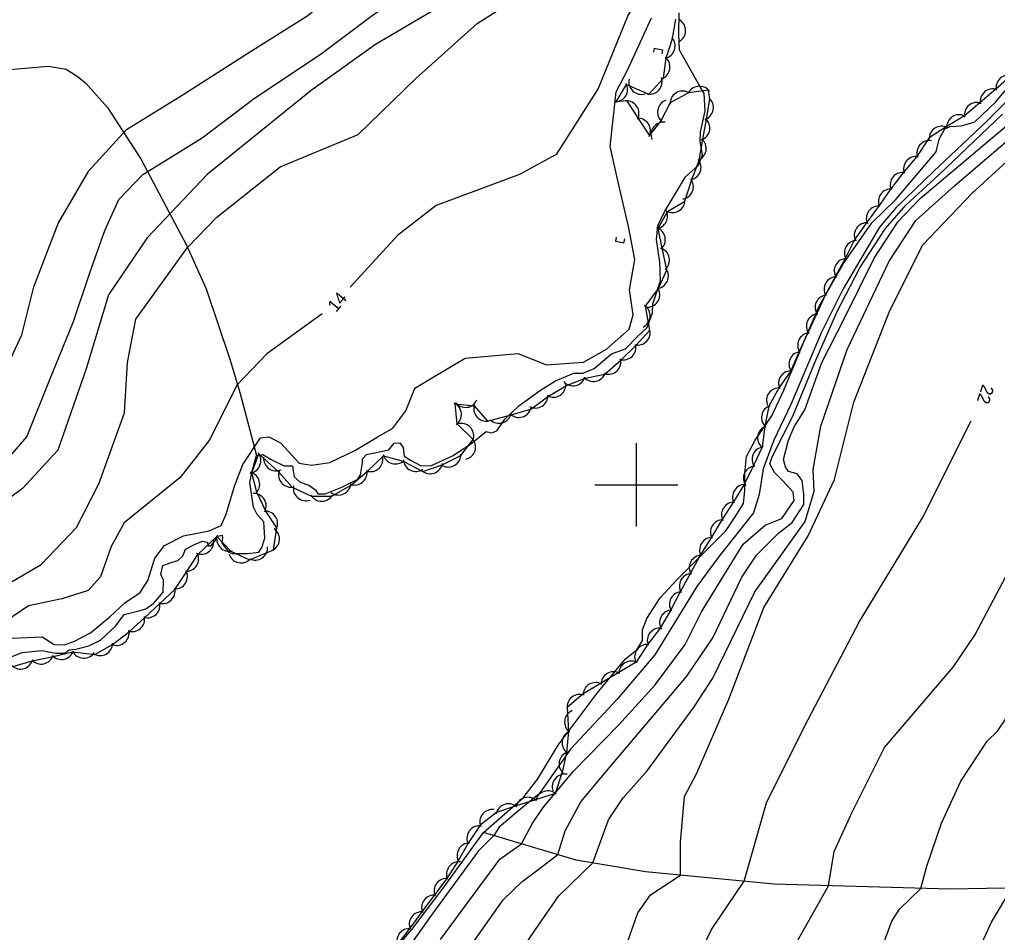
# Model space of a CAD drawing. Extents: x 646142 to 649934, y 5874075 to 5876351.
# Drawn here: x 648451.8 to 648686.8, y 5875292.5 to 5875511.8 of the extents above; entities that cross this region are included whole.
import ezdxf

# ---------------------------------------------------------------- set-up
doc = ezdxf.new("R2010")
doc.units = 0
for name, color, linetype in [('Niveau 1', 7, 'Continuous'), ('Niveau 2', 7, 'Continuous'), ('Niveau 26', 7, 'Continuous'), ('Niveau 4', 7, 'Continuous'), ('Niveau 44', 7, 'Continuous'), ('Niveau 61', 7, 'Continuous')]:
    doc.layers.add(name, color=color, linetype=linetype)

msp = doc.modelspace()

# ---------------------------------------------------------------- linework, layer by layer
at = {"layer": 'Niveau 1'}
for points in [[(648446.52, 5875403.47), (648453.53, 5875411.53), (648458.94, 5875424.95), (648464.76, 5875439.28), (648468.71, 5875450.92), (648472.32, 5875461.15), (648475.67, 5875468.58), (648481.42, 5875474.59), (648495.69, 5875483.36), (648508.29, 5875492.92), (648524.03, 5875503.43), (648536.21, 5875512.49), (648556.03, 5875526.54), (648567.28, 5875535.53), (648573.52, 5875544.1), (648582.86, 5875551.08), (648596.63, 5875560.03), (648610.78, 5875566.93), (648623.12, 5875576.45), (648636.69, 5875591.14), (648643.13, 5875598.74), (648651.26, 5875607.45), (648666.17, 5875621.46), (648679.59, 5875631.12)], [(648592.7, 5875275.42), (648600.38, 5875297.2), (648603.37, 5875301.49), (648610.59, 5875306.26), (648610.58, 5875314.15), (648611.6, 5875325.18), (648614.45, 5875330.61), (648622.21, 5875348.51), (648630.6, 5875370.52), (648641.28, 5875387.77), (648647.59, 5875401.32), (648652.28, 5875419.91), (648660.88, 5875441.9), (648668.86, 5875457.71), (648680.66, 5875470.07), (648694.75, 5875482.88), (648710.43, 5875501.6), (648716.29, 5875506.83)]]:
    msp.add_lwpolyline(points, dxfattribs=at)
at = {"layer": 'Niveau 2'}
for points in [[(648773.24, 5875660.13), (648771.63, 5875657.22), (648765.49, 5875651.86), (648760.19, 5875648.97), (648749.57, 5875645.79), (648733.26, 5875640.93), (648712.53, 5875636.85), (648693.47, 5875629.74), (648674.98, 5875618.92), (648656.72, 5875602.7), (648643.07, 5875587.36), (648618.42, 5875563.73), (648594.18, 5875540.59), (648565.49, 5875522.47), (648537.36, 5875505.81), (648521.88, 5875494.75), (648496.86, 5875474.58), (648482.48, 5875459.38), (648473.15, 5875445.67), (648467.81, 5875427.88), (648460.98, 5875408.35), (648452.47, 5875399.1), (648430.65, 5875382.97)], [(648751.16, 5875635.11), (648742.73, 5875629.52), (648734.81, 5875627.4), (648724.79, 5875625.09), (648709.54, 5875619.48), (648694.13, 5875610.32), (648675.4, 5875598.74), (648662.52, 5875584.84), (648654.97, 5875574.48), (648637.37, 5875558.02), (648621.93, 5875546.24), (648610.99, 5875534.16), (648598.03, 5875512.9), (648590.87, 5875495.22), (648580.72, 5875479.4), (648571.95, 5875474.59), (648551.87, 5875467.11), (648542.6, 5875459.89), (648531.28, 5875447.47)], [(648442.65, 5875372.58), (648456.97, 5875380.91), (648465.46, 5875389.73), (648470.84, 5875400.27), (648477.03, 5875417.31), (648477.73, 5875429.43), (648479.72, 5875439.79), (648492.14, 5875457.01), (648499.2, 5875464.3), (648514.42, 5875476.42), (648533.17, 5875484.19), (648546.9, 5875497.57), (648561.79, 5875510.81), (648580.89, 5875522.99), (648598.86, 5875537.86), (648613.32, 5875553.6), (648629.07, 5875567.35), (648649.25, 5875589.33), (648661.93, 5875600.98), (648676.7, 5875615.34), (648699.11, 5875628.2), (648705.3, 5875630.04)], [(648444.89, 5875420.22), (648452.31, 5875436.05), (648455.23, 5875447.59), (648461.09, 5875462.83), (648468.41, 5875475.42), (648477.53, 5875485.38), (648490.9, 5875493.61), (648507.31, 5875504.15), (648521.1, 5875512.75), (648525.4, 5875516.56), (648530.21, 5875524.32), (648533.29, 5875532.06), (648533.37, 5875536.39)], [(648546.75, 5875423.22), (648552.38, 5875426.58), (648558.9, 5875430.42), (648571.51, 5875431.56), (648578.45, 5875428.87), (648587.29, 5875429.47), (648592.82, 5875432.59), (648598.29, 5875437.39), (648599.24, 5875440.89), (648598.33, 5875446.85), (648599.63, 5875454.15), (648598.12, 5875462.04), (648595.74, 5875472.41), (648593.69, 5875481.3), (648595.14, 5875494.43), (648597.97, 5875499.76), (648603.61, 5875512.17)], [(648697.21, 5875500.45), (648684, 5875487.18), (648671.38, 5875475.27), (648662.47, 5875466.65), (648658.41, 5875461.89), (648649.69, 5875447.12), (648644.48, 5875436.69), (648637.09, 5875419.35), (648633.04, 5875410.71), (648630.48, 5875403.89), (648629.51, 5875397.71), (648628.15, 5875393.28), (648619.88, 5875382.91), (648614.53, 5875375.57), (648604.46, 5875359.18), (648595.5, 5875348.63), (648584.21, 5875336.53), (648576.69, 5875325.77), (648571.74, 5875321.81), (648567.03, 5875317.77), (648565.8, 5875315.74), (648562.04, 5875312.06), (648551.13, 5875297.15), (648545.6, 5875289.33)], [(648635.88, 5875404.37), (648635.37, 5875406.11), (648635.37, 5875406.11), (648636.59, 5875410.75), (648637.94, 5875413.98), (648640.51, 5875418.04), (648644.54, 5875429.39), (648649.95, 5875439.88), (648657.12, 5875454.47), (648662.93, 5875463.27), (648668.2, 5875468.82), (648678.92, 5875477.82), (648690.08, 5875487.21)], [(648653.73, 5875452.15), (648659.84, 5875461.58), (648664.76, 5875467.23), (648672.72, 5875474.45), (648688.02, 5875489.07)], [(648569.38, 5875283.74), (648575.8, 5875293.16), (648581.4, 5875301.31), (648589.58, 5875309.17), (648593.32, 5875319.5), (648596.83, 5875324.84), (648602.58, 5875331.34), (648613.87, 5875346.71), (648618.41, 5875353.57), (648628.5, 5875374.28), (648635.8, 5875384.51), (648640.6, 5875391.17), (648642.74, 5875398.51), (648642.5, 5875403.71), (648644.36, 5875414.11), (648650.67, 5875432.54), (648660.77, 5875453.75), (648667.18, 5875463.53), (648676.53, 5875471.92), (648692.46, 5875485.5)], [(648622.07, 5875247.3), (648629.59, 5875266.23), (648638.01, 5875289.19), (648646.2, 5875303.69), (648647.54, 5875311.94), (648651.78, 5875321.22), (648659.66, 5875336.91), (648676.17, 5875356.24), (648681.3, 5875363.87), (648690.29, 5875380.85), (648717.14, 5875420.67), (648722.82, 5875430.35), (648724.42, 5875434.72), (648725.25, 5875441.14), (648724.29, 5875451.86), (648726.2, 5875464.49)], [(648552.94, 5875290.82), (648567.2, 5875310.09), (648572.39, 5875313.77), (648575.01, 5875318.55), (648577.6, 5875322.5), (648584.94, 5875331.21), (648595.71, 5875342.28), (648604.5, 5875351.97), (648611.75, 5875361.63), (648615.63, 5875369.52), (648622.3, 5875380.31), (648625.69, 5875385.77), (648630.94, 5875390.34), (648634.93, 5875391.93), (648637.95, 5875396.29), (648637.65, 5875398.28), (648635.28, 5875400.9), (648633.2, 5875402.96), (648632.05, 5875405.1), (648632.61, 5875406.71), (648637.61, 5875416.5), (648642.91, 5875429.43), (648648.2, 5875441.47), (648653.73, 5875452.15)], [(648524.51, 5875441.07), (648511.25, 5875431.51), (648503.97, 5875423.96), (648497.56, 5875410.91), (648490.4, 5875401.74), (648476.91, 5875390.9)], [(648450.04, 5875363.15), (648457.23, 5875363.51), (648460.13, 5875361.66), (648462.51, 5875361.54), (648464.86, 5875362.37), (648468.86, 5875364.44), (648473.47, 5875368.3), (648477.06, 5875371.7), (648480.8, 5875374.11), (648482.59, 5875377.03), (648484.28, 5875382.39), (648486.6, 5875385.42), (648491.17, 5875387.73), (648497.33, 5875388.95), (648500.23, 5875390.25), (648501.46, 5875392.94), (648503.48, 5875399.71), (648505.48, 5875404.92), (648509.73, 5875411.31), (648511.73, 5875411.51), (648514.52, 5875410.12), (648518.95, 5875405.26), (648521.97, 5875404.77), (648526.36, 5875405.38), (648532.53, 5875408.35), (648537.74, 5875411.44), (648541.48, 5875413.61), (648544.62, 5875417.81), (648546.83, 5875423.43)], [(648558.35, 5875144.51), (648561.02, 5875146.56), (648564.53, 5875149.52), (648567.42, 5875152.64), (648570.45, 5875164.8), (648576.75, 5875176.03), (648582.31, 5875187.66), (648596.54, 5875228.87), (648603.08, 5875255.94), (648608.57, 5875273.45), (648618.1, 5875293.2), (648625.88, 5875304.77), (648631.24, 5875323.66), (648640.41, 5875341.95), (648653.65, 5875367.19), (648668.78, 5875392.12), (648680.45, 5875415.43)], [(648558.6, 5875287), (648567.97, 5875300.29), (648572.51, 5875304.66), (648576.04, 5875307.27), (648581.1, 5875311.17), (648582.92, 5875316.93), (648586.64, 5875323.84), (648593.53, 5875332.13), (648604.69, 5875345.25), (648612.12, 5875354.08), (648618.35, 5875363.26), (648625.37, 5875377.87), (648628.89, 5875383.1), (648634.18, 5875388.39), (648637.48, 5875390.98), (648640.26, 5875395.3), (648640.27, 5875397.8), (648639.85, 5875401.09), (648638.64, 5875402.63), (648636.58, 5875403.25), (648635.88, 5875404.37)], [(648476.91, 5875390.9), (648473.78, 5875385.22), (648471.27, 5875377.94), (648468.27, 5875374.67), (648461.97, 5875372.6), (648453.96, 5875370.97), (648448.41, 5875367.19)], [(648684.3, 5875338.42), (648686.77, 5875340.87), (648688.94, 5875344.01)], [(648625.98, 5875139.41), (648626.24, 5875144.08), (648628.96, 5875152.5), (648633.52, 5875169.83), (648636.38, 5875194.48), (648640.24, 5875216.68), (648642.14, 5875240.62), (648644.45, 5875250.49), (648649.68, 5875266), (648653.41, 5875273.59), (648661.4, 5875295.19), (648663.26, 5875298.06), (648668.38, 5875303.05), (648669.83, 5875308.41), (648673.35, 5875318.75), (648677.94, 5875328.85), (648684.3, 5875338.42)], [(648669.21, 5875174.05), (648673.22, 5875194.68), (648676.22, 5875210.96), (648681.89, 5875239.25), (648682.27, 5875249.4), (648680.98, 5875254.69), (648678.96, 5875264.27), (648678.37, 5875270.92), (648679.53, 5875278.9), (648682.11, 5875287.95), (648685.34, 5875294.94), (648690.22, 5875303.15), (648690.77, 5875307.43), (648692.74, 5875314.18), (648696.01, 5875323.29), (648699.48, 5875330.17), (648701.55, 5875334.47)]]:
    msp.add_lwpolyline(points, dxfattribs=at)
at = {"layer": 'Niveau 26'}
for p, q in [((648604.3, 5875504.94), (648604.11, 5875503.96)), ((648604.3, 5875504.94), (648606.28, 5875504.55)), ((648606.28, 5875504.55), (648606.09, 5875503.57)), ((648595.05, 5875458.51), (648595.25, 5875459.49)), ((648597.03, 5875458.11), (648597.23, 5875459.09)), ((648597.03, 5875458.11), (648595.05, 5875458.51))]:
    msp.add_line(p, q, dxfattribs=at)
at = {"layer": 'Niveau 4'}
for points in [[(648555.81, 5875406.98), (648560.16, 5875409.81), (648563.91, 5875412.81), (648565.25, 5875412.47), (648566.51, 5875412.95), (648568.37, 5875415.77), (648571.75, 5875418.97), (648576.97, 5875422.72), (648580.55, 5875424.99), (648584.99, 5875426.87), (648587.13, 5875426.84), (648589.87, 5875427.96), (648594.04, 5875431.48), (648597.37, 5875432.65), (648600.26, 5875435.67), (648602.63, 5875437.84), (648603.87, 5875441.31), (648603.94, 5875443.52), (648604.61, 5875445.43), (648605.84, 5875449.02), (648605.62, 5875453.53), (648604.87, 5875458.93), (648605.2, 5875462.21), (648606.8, 5875465.59), (648611.82, 5875474.01), (648614.96, 5875476.82), (648615.92, 5875479.33), (648615.34, 5875482.54), (648615.4, 5875484.75), (648616.52, 5875489.84), (648616.33, 5875494), (648615.28, 5875495.77), (648610.36, 5875504.44), (648610.19, 5875508.38), (648610.28, 5875513.38)], [(648447.65, 5875499.66), (648458.71, 5875500.56), (648463.03, 5875499.91), (648465.74, 5875498.11), (648467.65, 5875496.61), (648472.97, 5875490.68), (648481, 5875478.14), (648491.9, 5875457.61), (648496.62, 5875447.14), (648502.29, 5875430.2), (648504.8, 5875421.96), (648508.77, 5875407.04)], [(648609.73, 5875377.2), (648621.54, 5875389), (648623.72, 5875392.33), (648625.79, 5875395.52), (648626.09, 5875398.65), (648626.06, 5875402.83), (648626.51, 5875406.81), (648628.52, 5875410.71), (648632.59, 5875416.61), (648635.46, 5875422.74), (648640.52, 5875434.95), (648643.94, 5875442.97), (648649.76, 5875453.22), (648656.57, 5875462.97), (648662.33, 5875468.58), (648672.06, 5875480.01), (648672.73, 5875483.04), (648674.16, 5875485.54), (648675.41, 5875486.12), (648678.11, 5875486.25), (648681.33, 5875487.25), (648686.34, 5875491.96), (648693.81, 5875500.81)], [(648463.76, 5875360.39), (648465.29, 5875360.54), (648468.41, 5875361.33), (648471.25, 5875362.69), (648474.94, 5875366.16), (648476.94, 5875368.87), (648480.76, 5875369.85), (648482.14, 5875370.23), (648484.03, 5875371.61), (648486.27, 5875374.22), (648486.35, 5875377.1), (648485.75, 5875378.47), (648486.25, 5875380.67), (648488.2, 5875381.34), (648489.81, 5875381.86), (648491.01, 5875382.93), (648491.69, 5875384.55), (648493.83, 5875385.72), (648495.77, 5875386.52), (648496.98, 5875386.28), (648497.07, 5875385.33), (648497.77, 5875385.4), (648498.74, 5875386.45), (648499.45, 5875387.72), (648500.49, 5875387.94), (648500.56, 5875387.23), (648500.44, 5875386.03), (648502.07, 5875383.8), (648502.92, 5875383.53), (648506.59, 5875383.54), (648509.29, 5875383.81), (648510.01, 5875384.96), (648510.75, 5875387.18), (648510.5, 5875391.1), (648508.92, 5875392.85), (648508.03, 5875394.67), (648507.13, 5875400.55), (648507.79, 5875403.6), (648508.77, 5875407.04), (648510.28, 5875407.31), (648512.29, 5875406.08), (648515.39, 5875404.6), (648517.41, 5875404.57), (648517.52, 5875403.38), (648517.77, 5875401.97), (648519.2, 5875400.68), (648521.28, 5875399.94), (648522.93, 5875398.79), (648523.49, 5875397.89), (648525.27, 5875397.83), (648529.27, 5875399.43), (648533.11, 5875401.36), (648533.73, 5875402.38), (648534.17, 5875405.29), (648534.2, 5875406.25), (648535.16, 5875407.3), (648540.51, 5875408.43), (648541.78, 5875410), (648543.19, 5875410.14), (648544.01, 5875409.02), (648544.21, 5875406.89), (648545.71, 5875405.97), (648548.33, 5875404.56), (648550.81, 5875404.69), (648555.81, 5875406.98)], [(648538.93, 5875284.84), (648546.07, 5875293.18), (648553.55, 5875303.11), (648563.3, 5875316.49), (648572.82, 5875324.83), (648576.3, 5875329.35), (648581.23, 5875337.48), (648590.6, 5875349.99), (648597.41, 5875358.19), (648600.16, 5875360.37), (648601.49, 5875362.65), (648601.49, 5875365.16), (648602.54, 5875367.89), (648605.75, 5875372.86), (648609.73, 5875377.2)], [(648446.29, 5875357.32), (648452.45, 5875359.73), (648457.15, 5875360.2), (648460.52, 5875359.59), (648462.66, 5875359.56), (648463.76, 5875360.39)], [(648785.38, 5875300.42), (648761.34, 5875301.73), (648735.42, 5875302.25), (648710.3, 5875303.55), (648675.42, 5875302.85), (648633.06, 5875304.07), (648602.22, 5875307.07), (648585.58, 5875309.83), (648563.3, 5875316.49)]]:
    msp.add_lwpolyline(points, dxfattribs=at)
at = {"layer": 'Niveau 44'}
for points in [[(648602.24, 5875442.93), (648605.34, 5875447.22), (648607.3, 5875451.66), (648606.19, 5875456.87), (648605.21, 5875461.63), (648607.5, 5875465.67), (648611.68, 5875468.14), (648613.3, 5875473.39), (648615.09, 5875477.9), (648615.98, 5875483.02), (648616.83, 5875487.8), (648617.7, 5875492.73), (648617.35, 5875494.81), (648612.53, 5875494.2), (648608.11, 5875491.77), (648605.91, 5875487.47), (648603.2, 5875484.01), (648600.53, 5875488.06), (648597.78, 5875492.24), (648595.12, 5875492.04), (648597.67, 5875496.17), (648603, 5875493.84), (648606.49, 5875497.72), (648607.18, 5875502.52), (648608.72, 5875507.24), (648609.53, 5875511.88)], [(648690.11, 5875498.32), (648686.43, 5875495.15), (648682.53, 5875491.8), (648678.85, 5875488.63), (648674.45, 5875486), (648670.39, 5875483.34), (648667.42, 5875478.9), (648664.3, 5875475.18), (648661.13, 5875471.1), (648658.32, 5875467.15), (648655.33, 5875462.96), (648652.51, 5875459), (648650.19, 5875454.36), (648647.83, 5875450.12), (648645.36, 5875445.58), (648643.34, 5875441.17), (648641.18, 5875436.5), (648639.16, 5875432.08), (648637.12, 5875427.4), (648634.32, 5875423.43), (648631.83, 5875418.91), (648630.9, 5875414.14), (648630.2, 5875409.07), (648628.19, 5875404.65), (648625.91, 5875400.08), (648623.33, 5875395.97), (648620.57, 5875391.62), (648618.04, 5875387.48), (648615.32, 5875383.1), (648613.01, 5875378.82), (648610.57, 5875374.3), (648608.26, 5875370.02), (648605.73, 5875365.61), (648602.76, 5875361.76), (648599.98, 5875357.43), (648595.82, 5875354.93), (648591.4, 5875352.28), (648587.24, 5875349.78), (648583.37, 5875346.55), (648583.71, 5875340.82), (648583.22, 5875335.72), (648582.2, 5875330.97), (648580.52, 5875325.9), (648575.76, 5875324.37), (648571.14, 5875322.89), (648566.39, 5875321.29), (648562.51, 5875318.22), (648559.57, 5875313.97), (648557.23, 5875309.71), (648554.43, 5875305.45), (648551.53, 5875301.55), (648548.46, 5875297.43), (648545.57, 5875293.53), (648542.47, 5875289.43)], [(648450.21, 5875356.38), (648454.86, 5875357.74), (648459.89, 5875358.8), (648464.62, 5875359.87), (648469.9, 5875359.26), (648474.13, 5875361.63), (648478.21, 5875364.82), (648481.84, 5875368.04), (648485.62, 5875371.56), (648489.14, 5875374.89), (648492.02, 5875379.22), (648494.63, 5875383.31), (648499.21, 5875387.62), (648502.54, 5875384.09), (648507.04, 5875382.03), (648512.81, 5875384.4), (648513.61, 5875389.65), (648510.96, 5875393.72), (648508.82, 5875398.23), (648507.61, 5875402.93), (648509.3, 5875407.43), (648514.1, 5875403.08), (648517.34, 5875399.46), (648521.98, 5875397.3), (648526.84, 5875397.29), (648531.58, 5875400.05), (648535.29, 5875403.18), (648539.27, 5875406.99), (648543.94, 5875405.68), (648548.74, 5875403.22), (648553.33, 5875404.8), (648557.82, 5875407.07), (648560.79, 5875410.92), (648556.94, 5875414.67), (648556.51, 5875419.5), (648561, 5875418.96), (648564.23, 5875415.34), (648569.96, 5875416.82), (648574.62, 5875418.19), (648578.89, 5875421.3), (648583.04, 5875423.83), (648587.69, 5875425.63), (648592.43, 5875426.64), (648596.37, 5875430.08), (648599.87, 5875433.45), (648603.25, 5875437.15), (648602.24, 5875442.93)]]:
    msp.add_lwpolyline(points, dxfattribs=at)
for centre, start, end in [((648608.84, 5875509.14), 298.4679, 58.4459), ((648606.31, 5875505.45), 282.4118, 42.3897), ((648605.09, 5875500.37), 291.8832, 51.8612), ((648601.18, 5875496.82), 167.8536, 287.8315), ((648603.2, 5875496.84), 260.2229, 20.2008), ((648689.42, 5875495.4), 70.7361, 190.714), ((648594.89, 5875495.03), 268.3345, 28.3124), ((648611.11, 5875491.63), 63.2973, 183.2752), ((648615.16, 5875492.76), 37.1205, 157.0984), ((648685.63, 5875492.14), 70.7361, 190.714), ((648597.64, 5875489.24), 333.3961, 93.374), ((648608.08, 5875489.55), 109.7578, 229.7358), ((648615.54, 5875490.64), 289.9749, 49.9529), ((648681.84, 5875488.88), 70.7361, 190.714), ((648600.39, 5875485.07), 333.3961, 93.374), ((648614.67, 5875485.72), 289.9749, 49.9529), ((648677.57, 5875485.93), 63.1708, 183.1488), ((648606.52, 5875484.14), 82.345, 202.3229), ((648673.38, 5875483.19), 63.1708, 183.1488), ((648613.8, 5875480.8), 289.9749, 49.9529), ((648670.43, 5875479.73), 79.9764, 199.9544), ((648612.55, 5875476.3), 278.3403, 38.3183), ((648667.21, 5875475.9), 79.9764, 199.9544), ((648610.71, 5875471.65), 278.3403, 38.3183), ((648663.99, 5875472.08), 79.9764, 199.9544), ((648661.16, 5875468.1), 84.5437, 204.5217), ((648608.7, 5875468.42), 240.5752, 0.5531), ((648604.52, 5875464.56), 284.8616, 34.7972), ((648658.26, 5875464.03), 84.5437, 204.5217), ((648603.97, 5875458.9), 311.5541, 71.532), ((648655.36, 5875459.96), 84.5437, 204.5217), ((648604.97, 5875454), 311.4934, 71.4713), ((648652.99, 5875455.75), 90.884, 210.862), ((648650.55, 5875451.38), 90.884, 210.862), ((648604.71, 5875450.15), 276.2704, 36.2484), ((648648.12, 5875447.01), 90.884, 210.862), ((648602.63, 5875445.68), 273.4082, 33.3862), ((648645.95, 5875442.64), 95.3276, 215.3056), ((648600.3, 5875440.63), 295.8599, 55.8378), ((648643.86, 5875438.1), 95.3276, 215.3056), ((648600.31, 5875436.57), 257.2332, 17.2111), ((648641.77, 5875433.55), 95.3276, 215.3056), ((648596.9, 5875433.04), 253.9082, 13.8861), ((648639.68, 5875429.01), 95.3276, 215.3056), ((648593.29, 5875429.57), 253.9082, 13.8861), ((648589.69, 5875427.86), 221.9884, 341.9663), ((648637.16, 5875424.4), 84.8211, 204.799), ((648580.05, 5875424.07), 241.3788, 1.3568), ((648584.8, 5875426.82), 221.9884, 341.9663), ((648575.78, 5875421.47), 241.3788, 1.3568), ((648634.28, 5875420.31), 84.8211, 204.799), ((648554.97, 5875416.93), 305.0322, 65.0102), ((648558.94, 5875421.61), 217.3612, 337.3391), ((648563.93, 5875418.33), 161.8112, 281.7892), ((648566.99, 5875417.79), 226.3274, 346.3054), ((648571.79, 5875419.2), 226.3274, 346.3054), ((648633.09, 5875416.19), 108.9614, 228.9393), ((648557.94, 5875411.78), 346.1291, 106.107), ((648632.13, 5875411.28), 108.9614, 228.9393), ((648558.39, 5875409.12), 282.9012, 42.8791), ((648506.78, 5875405.82), 278.5778, 38.5558), ((648542.08, 5875408.03), 194.2684, 314.2463), ((648554.83, 5875407.29), 241.8059, 1.7839), ((648630.8, 5875406.13), 95.5635, 215.5415), ((648513.43, 5875406.38), 174.716, 294.6939), ((648536.12, 5875406.19), 250.1598, 10.1377), ((648547.01, 5875406.24), 184.2567, 304.2347), ((648550.47, 5875405.68), 228.9914, 348.9693), ((648506.5, 5875400.14), 314.4239, 74.4018), ((648517.04, 5875402.44), 161.7939, 281.7719), ((648532.3, 5875402.97), 250.1598, 10.1377), ((648628.73, 5875401.57), 95.5635, 215.5415), ((648528.45, 5875400.57), 233.9824, 353.9604), ((648508.07, 5875394.91), 333.156, 93.134), ((648520.58, 5875399.2), 168.9308, 288.9087), ((648626.11, 5875397.09), 87.9277, 207.9057), ((648524.41, 5875399.06), 209.9299, 329.9078), ((648623.46, 5875392.85), 87.9277, 207.9057), ((648510.81, 5875390.72), 333.156, 93.134), ((648620.81, 5875388.63), 88.5118, 208.4897), ((648511.27, 5875386.97), 295.0506, 55.0286), ((648495.45, 5875386.32), 246.5656, 6.5435), ((648502.16, 5875387.06), 163.3361, 283.314), ((648618.2, 5875384.37), 88.5118, 208.4897), ((648508.41, 5875384.94), 243.6091, 3.587), ((648491.84, 5875382.22), 267.401, 27.3789), ((648505.03, 5875384.26), 197.9558, 317.9337), ((648615.72, 5875380.12), 91.6624, 211.6404), ((648489.15, 5875378.01), 267.401, 27.3789), ((648613.34, 5875375.72), 91.6624, 211.6404), ((648486.17, 5875374.5), 253.4511, 13.4291), ((648610.97, 5875371.32), 91.6624, 211.6404), ((648482.53, 5875371.07), 253.4511, 13.4291), ((648608.59, 5875366.92), 91.6624, 211.6404), ((648478.86, 5875367.75), 251.5574, 11.5353), ((648475.11, 5875364.44), 251.5574, 11.5353), ((648605.64, 5875362.61), 82.3762, 202.3542), ((648471.15, 5875361.98), 239.272, 359.2499), ((648602.59, 5875358.65), 82.3762, 202.3542), ((648452.04, 5875358.75), 226.3109, 346.2888), ((648456.99, 5875359.95), 222.7713, 342.7493), ((648461.86, 5875361.06), 222.7713, 342.7493), ((648467.22, 5875361.37), 206.9875, 326.9654), ((648598.8, 5875354.67), 61.0159, 180.9939), ((648594.52, 5875352.1), 61.0159, 180.9939), ((648590.23, 5875349.52), 61.0159, 180.9939), ((648586.37, 5875346.67), 68.2793, 188.2572), ((648585.76, 5875343.02), 113.0369, 233.0148), ((648585.15, 5875338.05), 113.0369, 233.0148), ((648584.43, 5875332.97), 107.8516, 227.8295), ((648582.81, 5875327.53), 78.9036, 198.8815), ((648578.75, 5875323.48), 47.7847, 167.7626), ((648569.26, 5875320.4), 48.6589, 168.6368), ((648573.99, 5875321.95), 47.7847, 167.7626), ((648565.4, 5875319.02), 81.5214, 201.4994), ((648562.29, 5875315.11), 81.5214, 201.4994), ((648559.94, 5875310.99), 91.1534, 211.1313), ((648557.38, 5875306.46), 83.386, 203.3639), ((648554.4, 5875302.45), 83.386, 203.3639), ((648551.41, 5875298.44), 83.386, 203.3639), ((648548.43, 5875294.43), 83.386, 203.3639), ((648545.45, 5875290.41), 83.386, 203.3639)]:
    msp.add_arc(centre, 3, start, end, dxfattribs=at)
at = {"layer": 'Niveau 61'}
for points in [[(648600, 5875410), (648600, 5875400), (648600, 5875390)], [(648590, 5875400), (648600, 5875400), (648610, 5875400)]]:
    msp.add_lwpolyline(points, dxfattribs=at)

# ---------------------------------------------------------------- texts
at = {"layer": 'Niveau 2'}
for s, rotation, p in [('14', 50.3587, (648527.85, 5875441.31)), ('22', 251.6371, (648683.18, 5875424.32))]:
    msp.add_text(s, height=3, rotation=rotation, dxfattribs=at).set_placement(p)

doc.saveas('drawing.dxf')
